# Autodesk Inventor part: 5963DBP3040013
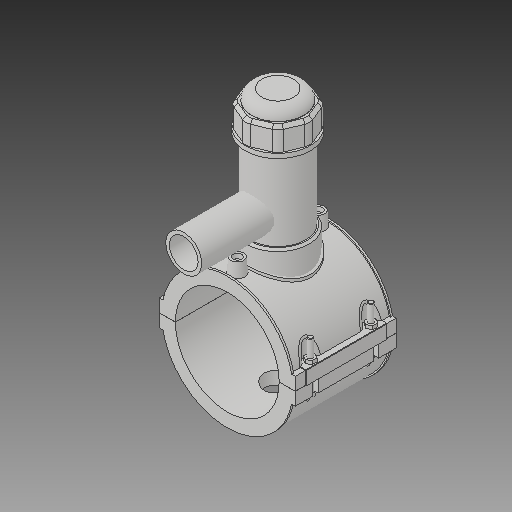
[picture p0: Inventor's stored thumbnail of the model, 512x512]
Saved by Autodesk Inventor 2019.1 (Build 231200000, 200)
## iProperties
Created: 2017-07
Part Number: 5963DBP3040013
Material: Generic
Description: PLASSON TAPPING SADDLE 4''DIPS x 1 1/4''IPS
Document SubType Name: Modeling
Designer: KIM
Density: 1 g/cm^3
Appearance: Default
Author: KIM
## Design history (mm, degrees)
derived "5963DBP_5963BUP.ipt"
feature "Solid1::5963DBP_5963BUP.ipt"
feature "Solid2::5963DBP_5963BUP.ipt"
feature "Solid3::5963DBP_5963BUP.ipt"
tag "TaggingFeature1"
body "Solid1"
body "Solid2"
body "Solid3"
other parameters: "d0" = 121.3, "d2" = 159.004, "d3" = 30.325, "d4" = 118.11, "d5" = 0, "d6" = 0.1, "d8" = 0, "d19" = 6, "d20" = 6, "d21" = 70.866, "d23" = 0, "d24" = 35.433, "d26" = 0, "d27" = 3, "d28" = 3, "d29" = 3, "d30" = 40.43333, "d31" = 6, "d32" = 0, "d33" = 0, "d34" = 0.6, "d40" = 78.21424, "d41" = 76.419, "d43" = 0, "d45" = 0, "d47" = 146.072, "d70" = 15, "d72" = 0, "d73" = 6, "d75" = 5, "d76" = 0, "d77" = 6.065, "d78" = 90.65, "d79" = 15, "d80" = 47.244, "d82" = 5 deg, "d84" = 4, "d85" = 14, "d86" = 0, "d87" = 3, "d88" = 0, "d89" = 1, "d90" = 1, "d91" = 94.488, "d92" = 0, "d93" = 0.5, "d94" = 63.84211, "d96" = 153.42024, "d97" = 2.3622, "d98" = 0, "d120" = 140 deg, "d121" = 24.228, "d122" = 20 deg, "d123" = 300.824, "d124" = 90.2472, "d126" = 0, "d143" = 124.939, "d145" = 22.39385, "d149" = 1.8195, "d150" = 24.63323, "d153" = 118.11, "d154" = 0, "d156" = 75.206, "d157" = 160 deg, "d159" = 5.8224, "d161" = 1.8195, "d162" = 70.866, "d163" = 0, "d164" = 60.65, "d167" = 12.13, "d168" = 73.37171, "d170" = 3.4335, "d172" = 0, "d173" = 1, "d175" = 60.65, "d176" = 20 deg, "d177" = 8.491, "d178" = 29.112, "d180" = 0, "d183" = 11.6448, "d184" = 6.7928, "d185" = 38.38575, "d186" = 38.38575, "d187" = 75.206, "d188" = 8.7336, "d189" = 8.491, "d190" = 0, "d191" = 112.809, "d193" = 7.3248, "d194" = 4.13385, "d195" = 90 deg, "d197" = 0, "d199" = 0, "d200" = 14.556, "d202" = 0, "d203" = 177.038, "d204" = 72.59805, "d205" = 53.4933, "d206" = 64.95615, "d207" = 132.7785, "d208" = 138.08964, "d209" = 164.64534, "d210" = 65.72034, "d211" = 76.419, "d212" = 61.1352, "d213" = 39.5766, "d216" = 0, "d217" = 12.13, "d218" = 12.13, "d219" = 2.426, "d222" = 121.3, "d224" = 0, "d225" = 65.024, "d226" = 42.1, "d227" = 33.68, "d228" = 109.982, "d230" = 3.639, "d_" = 121.3, "B_" = 159.004, "L_" = 118.11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
